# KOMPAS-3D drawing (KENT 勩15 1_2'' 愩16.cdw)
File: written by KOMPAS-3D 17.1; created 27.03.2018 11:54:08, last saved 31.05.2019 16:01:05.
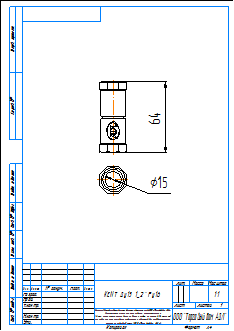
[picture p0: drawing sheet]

Sheet 1: A4, portrait

Title block, sheet 1: name: KENT Ду15 1_2'' Ру16; material: Внимание! Данный продукт является объектом авторского права ООО «Торговый Дом АДЛ». / Запрещается изменение, копирование, распространение / (в том числе путем копирования на другие сайты и ресурсы в Интернете) / или любое иное использование информации и объектов без предварительного / согласия правообладателя (ООО «Торговый Дом АДЛ»).; sheets: 1; organisation: ООО "Торговый дом АДЛ"; sheet format: A4; stored path: \\adlc.lan\data\АДЛ_ПКД\3D-модели\Поставщики\Standard Hidraulica\Латунный обратный клапан KENT PN16\KOMPAS 2D\KENT Ду15 1_2'' Ру16.cdw

Views: Вид 1, Проекционный вид 2
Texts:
  kka
  adl
Dimensions and other numbers on the sheet: 64; 15; 1:1; 1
